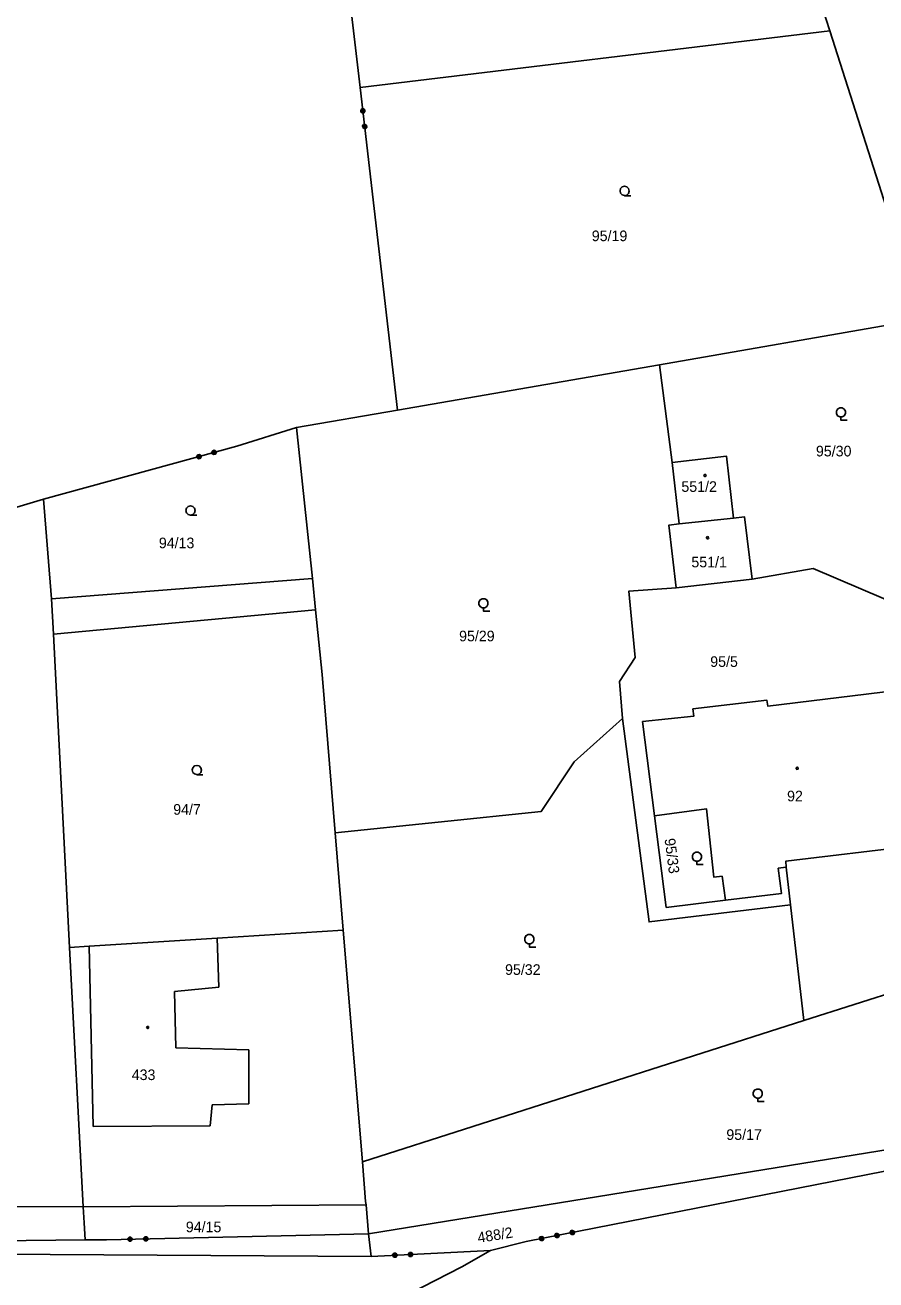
# Model space of a CAD drawing. Extents: x -757994 to -755874, y -1047691 to -1046119.
# Drawn here: x -757159.2 to -757091.1, y -1047392.5 to -1047292 of the extents above; entities that cross this region are included whole.
import ezdxf

# ---------------------------------------------------------------- set-up
doc = ezdxf.new("R2010")
doc.units = 0
doc.layers.add('katastrální mapa', color=7, linetype='Continuous')

msp = doc.modelspace()

# ---------------------------------------------------------------- linework, layer by layer
at = {"layer": 'katastrální mapa'}
for p, q in [((-757133.98, -1047283.45), (-757132.41, -1047297.02)), ((-757094.83, -1047292.5), (-757096.23, -1047288.12)), ((-757094.83, -1047292.5), (-757132.41, -1047297.02)), ((-757087.45, -1047315.58), (-757094.83, -1047292.5)), ((-757132.41, -1047297.02), (-757129.42, -1047322.85)), ((-757087.45, -1047315.58), (-757108.45, -1047319.22)), ((-757108.45, -1047319.22), (-757129.42, -1047322.85)), ((-757108.45, -1047319.22), (-757107.43, -1047327.04)), ((-757129.42, -1047322.85), (-757137.5, -1047324.25)), ((-757137.5, -1047324.25), (-757142.27, -1047325.75)), ((-757137.5, -1047324.25), (-757136.22, -1047336.33)), ((-757142.27, -1047325.75), (-757157.75, -1047329.98)), ((-757106.87, -1047331.97), (-757107.43, -1047327.04)), ((-757157.75, -1047329.98), (-757166.62, -1047332.62)), ((-757157.75, -1047329.98), (-757157.11, -1047337.95)), ((-757106.87, -1047331.97), (-757102.52, -1047331.51)), ((-757157.11, -1047337.95), (-757136.22, -1047336.33)), ((-757136.22, -1047336.33), (-757135.97, -1047338.84)), ((-757101.04, -1047336.38), (-757107.11, -1047337.08)), ((-757157.11, -1047337.95), (-757156.96, -1047340.78)), ((-757156.96, -1047340.78), (-757135.97, -1047338.84)), ((-757135.97, -1047338.84), (-757135.45, -1047344.01)), ((-757155.66, -1047365.86), (-757156.96, -1047340.78)), ((-757135.45, -1047344.01), (-757134.4, -1047356.7)), ((-757108.85, -1047355.32), (-757109.81, -1047347.77)), ((-757134.4, -1047356.7), (-757133.76, -1047364.47)), ((-757098.31, -1047359.44), (-757098.96, -1047359.53)), ((-757098.31, -1047359.44), (-757097.97, -1047362.46)), ((-757103.43, -1047360.15), (-757103.16, -1047362.08)), ((-757097.97, -1047362.46), (-757096.89, -1047371.72)), ((-757143.84, -1047365.11), (-757133.76, -1047364.47)), ((-757133.76, -1047364.47), (-757132.23, -1047383.02)), ((-757154.11, -1047365.76), (-757143.84, -1047365.11)), ((-757143.84, -1047365.11), (-757143.72, -1047369.05)), ((-757155.66, -1047365.86), (-757154.11, -1047365.76)), ((-757155.66, -1047365.86), (-757154.58, -1047386.63)), ((-757153.79, -1047380.19), (-757154.11, -1047365.76)), ((-757080.55, -1047366.5), (-757096.89, -1047371.72)), ((-757143.72, -1047369.05), (-757147.27, -1047369.39)), ((-757147.27, -1047369.39), (-757147.16, -1047373.89)), ((-757096.89, -1047371.72), (-757132.23, -1047383.02)), ((-757147.16, -1047373.89), (-757141.32, -1047374.07)), ((-757141.32, -1047374.07), (-757141.31, -1047378.37)), ((-757144.24, -1047378.47), (-757144.4, -1047380.15)), ((-757141.31, -1047378.37), (-757144.24, -1047378.47)), ((-757144.4, -1047380.15), (-757153.79, -1047380.19)), ((-757131.75, -1047388.8), (-757088.32, -1047381.73)), ((-757132.23, -1047383.02), (-757131.97, -1047386.19)), ((-757119.12, -1047389.4), (-757089.06, -1047383.51)), ((-757154.58, -1047386.63), (-757176.95, -1047386.56)), ((-757154.58, -1047386.63), (-757131.94, -1047386.46)), ((-757131.97, -1047386.19), (-757131.94, -1047386.46)), ((-757131.94, -1047386.46), (-757131.75, -1047388.8)), ((-757154.58, -1047386.63), (-757154.49, -1047387.91)), ((-757154.43, -1047389.27), (-757154.49, -1047387.91)), ((-757176.93, -1047389.56), (-757154.43, -1047389.27)), ((-757154.43, -1047389.27), (-757152.72, -1047389.26)), ((-757152.72, -1047389.26), (-757131.75, -1047388.8)), ((-757131.75, -1047388.8), (-757131.52, -1047390.59)), ((-757121.98, -1047390.12), (-757119.12, -1047389.4)), ((-757131.52, -1047390.59), (-757181.2, -1047390.32)), ((-757131.52, -1047390.59), (-757121.98, -1047390.12)), ((-757124.28, -1047391.44), (-757121.98, -1047390.12)), ((-757128.48, -1047393.6), (-757124.28, -1047391.44))]:
    msp.add_line(p, q, dxfattribs=at)
for points in [[(-757132.03, -1047298.95), (-757132.11, -1047299.06), (-757132.24, -1047299.07), (-757132.35, -1047298.99), (-757132.36, -1047298.86), (-757132.28, -1047298.75), (-757132.15, -1047298.74), (-757132.04, -1047298.82), (-757132.03, -1047298.95), (-757132.05, -1047298.95), (-757132.06, -1047298.83), (-757132.1, -1047298.8), (-757132.08, -1047299), (-757132.12, -1047299.04), (-757132.15, -1047298.76), (-757132.19, -1047298.77), (-757132.16, -1047299.04), (-757132.2, -1047299.05), (-757132.23, -1047298.77), (-757132.27, -1047298.78), (-757132.24, -1047299.05), (-757132.28, -1047299.02), (-757132.3, -1047298.82), (-757132.34, -1047298.86), (-757132.32, -1047298.98)], [(-757131.88, -1047300.2), (-757131.96, -1047300.3), (-757132.1, -1047300.32), (-757132.2, -1047300.23), (-757132.22, -1047300.1), (-757132.14, -1047299.99), (-757132, -1047299.98), (-757131.9, -1047300.06), (-757131.88, -1047300.2), (-757131.9, -1047300.18), (-757131.92, -1047300.06), (-757131.96, -1047300.03), (-757131.94, -1047300.23), (-757131.97, -1047300.27), (-757132.01, -1047299.99), (-757132.04, -1047300), (-757132.01, -1047300.28), (-757132.05, -1047300.28), (-757132.08, -1047300), (-757132.12, -1047300.01), (-757132.09, -1047300.29), (-757132.14, -1047300.25), (-757132.16, -1047300.05), (-757132.19, -1047300.1), (-757132.18, -1047300.21)], [(-757111.24, -1047305.68), (-757111.43, -1047305.63), (-757111.57, -1047305.5), (-757111.61, -1047305.31), (-757111.57, -1047305.12), (-757111.43, -1047304.99), (-757111.24, -1047304.94), (-757111.06, -1047304.99), (-757110.93, -1047305.12), (-757110.88, -1047305.32), (-757110.93, -1047305.51), (-757111.06, -1047305.64), (-757111.25, -1047305.69), (-757110.75, -1047305.69)], [(-757093.93, -1047323.4), (-757094.03, -1047323.4), (-757094.2, -1047323.3), (-757094.29, -1047323.13), (-757094.29, -1047322.94), (-757094.2, -1047322.77), (-757094.03, -1047322.67), (-757093.83, -1047322.67), (-757093.66, -1047322.77), (-757093.57, -1047322.94), (-757093.57, -1047323.13), (-757093.66, -1047323.3), (-757093.83, -1047323.4), (-757093.93, -1047323.4), (-757093.93, -1047323.66), (-757093.43, -1047323.66)], [(-757144.12, -1047326.42), (-757144.24, -1047326.36), (-757144.28, -1047326.23), (-757144.21, -1047326.11), (-757144.08, -1047326.07), (-757143.96, -1047326.14), (-757143.93, -1047326.27), (-757143.99, -1047326.39), (-757144.12, -1047326.42), (-757144.12, -1047326.4), (-757144.01, -1047326.37), (-757143.98, -1047326.32), (-757144.17, -1047326.37), (-757144.22, -1047326.35), (-757143.95, -1047326.27), (-757143.96, -1047326.23), (-757144.23, -1047326.31), (-757144.24, -1047326.27), (-757143.97, -1047326.19), (-757143.98, -1047326.16), (-757144.25, -1047326.23), (-757144.23, -1047326.18), (-757144.03, -1047326.13), (-757144.08, -1047326.1), (-757144.2, -1047326.13)], [(-757145.33, -1047326.75), (-757145.45, -1047326.68), (-757145.48, -1047326.55), (-757145.41, -1047326.44), (-757145.28, -1047326.4), (-757145.17, -1047326.47), (-757145.13, -1047326.6), (-757145.2, -1047326.72), (-757145.33, -1047326.75), (-757145.32, -1047326.73), (-757145.2, -1047326.7), (-757145.18, -1047326.65), (-757145.37, -1047326.7), (-757145.42, -1047326.67), (-757145.15, -1047326.6), (-757145.16, -1047326.56), (-757145.43, -1047326.63), (-757145.44, -1047326.6), (-757145.17, -1047326.52), (-757145.18, -1047326.48), (-757145.45, -1047326.56), (-757145.42, -1047326.51), (-757145.23, -1047326.45), (-757145.28, -1047326.43), (-757145.39, -1047326.46)], [(-757107.43, -1047327.04), (-757103.1, -1047326.54), (-757102.52, -1047331.51)], [(-757145.98, -1047331.25), (-757146.17, -1047331.2), (-757146.3, -1047331.07), (-757146.35, -1047330.88), (-757146.3, -1047330.7), (-757146.17, -1047330.56), (-757145.98, -1047330.51), (-757145.8, -1047330.56), (-757145.67, -1047330.7), (-757145.61, -1047330.89), (-757145.67, -1047331.08), (-757145.8, -1047331.21), (-757145.99, -1047331.26), (-757145.49, -1047331.26)], [(-757107.11, -1047337.08), (-757107.71, -1047332.07), (-757106.87, -1047331.97)], [(-757102.52, -1047331.51), (-757101.65, -1047331.39), (-757101.04, -1047336.38)], [(-757101.04, -1047336.38), (-757096.14, -1047335.54), (-757082.9, -1047341.2)], [(-757111.4, -1047347.55), (-757111.66, -1047344.59), (-757110.39, -1047342.66), (-757110.9, -1047337.34), (-757107.11, -1047337.08)], [(-757122.54, -1047338.67), (-757122.64, -1047338.67), (-757122.81, -1047338.58), (-757122.9, -1047338.41), (-757122.9, -1047338.22), (-757122.81, -1047338.04), (-757122.64, -1047337.95), (-757122.44, -1047337.95), (-757122.27, -1047338.04), (-757122.18, -1047338.22), (-757122.18, -1047338.41), (-757122.27, -1047338.58), (-757122.44, -1047338.67), (-757122.54, -1047338.67), (-757122.54, -1047338.94), (-757122.04, -1047338.94)], [(-757109.81, -1047347.77), (-757105.7, -1047347.34), (-757105.77, -1047346.77), (-757099.87, -1047346.07), (-757099.78, -1047346.54), (-757089.52, -1047345.31), (-757089.13, -1047349.43), (-757087.19, -1047349.2), (-757086.17, -1047349.84)], [(-757134.4, -1047356.7), (-757117.92, -1047354.98), (-757115.27, -1047351), (-757111.4, -1047347.55)], [(-757111.4, -1047347.55), (-757109.28, -1047363.82), (-757097.97, -1047362.46)], [(-757086.17, -1047349.84), (-757085.87, -1047352.5), (-757086.64, -1047353.43), (-757088.55, -1047353.69), (-757088.06, -1047357.72), (-757098.35, -1047358.96), (-757098.31, -1047359.44)], [(-757145.48, -1047352.03), (-757145.67, -1047351.98), (-757145.8, -1047351.85), (-757145.85, -1047351.66), (-757145.8, -1047351.48), (-757145.67, -1047351.34), (-757145.48, -1047351.29), (-757145.3, -1047351.34), (-757145.17, -1047351.48), (-757145.11, -1047351.67), (-757145.17, -1047351.86), (-757145.3, -1047351.99), (-757145.49, -1047352.04), (-757144.99, -1047352.04)], [(-757103.43, -1047360.15), (-757104.09, -1047360.24), (-757104.69, -1047354.76), (-757108.85, -1047355.32)], [(-757108.85, -1047355.32), (-757107.91, -1047362.66), (-757103.16, -1047362.08)], [(-757105.46, -1047358.97), (-757105.55, -1047358.97), (-757105.73, -1047358.87), (-757105.82, -1047358.7), (-757105.82, -1047358.51), (-757105.73, -1047358.34), (-757105.55, -1047358.24), (-757105.36, -1047358.24), (-757105.19, -1047358.34), (-757105.1, -1047358.51), (-757105.1, -1047358.7), (-757105.19, -1047358.87), (-757105.36, -1047358.97), (-757105.46, -1047358.97), (-757105.46, -1047359.23), (-757104.96, -1047359.23)], [(-757103.16, -1047362.08), (-757098.68, -1047361.54), (-757098.96, -1047359.53)], [(-757118.87, -1047365.57), (-757118.97, -1047365.57), (-757119.14, -1047365.47), (-757119.23, -1047365.3), (-757119.23, -1047365.11), (-757119.14, -1047364.93), (-757118.97, -1047364.84), (-757118.77, -1047364.84), (-757118.6, -1047364.93), (-757118.51, -1047365.11), (-757118.51, -1047365.3), (-757118.6, -1047365.47), (-757118.77, -1047365.57), (-757118.86, -1047365.57), (-757118.86, -1047365.83), (-757118.36, -1047365.83)], [(-757100.58, -1047377.92), (-757100.67, -1047377.92), (-757100.85, -1047377.83), (-757100.94, -1047377.66), (-757100.94, -1047377.47), (-757100.85, -1047377.29), (-757100.67, -1047377.2), (-757100.48, -1047377.2), (-757100.31, -1047377.29), (-757100.22, -1047377.47), (-757100.22, -1047377.66), (-757100.31, -1047377.83), (-757100.48, -1047377.92), (-757100.58, -1047377.92), (-757100.58, -1047378.19), (-757100.08, -1047378.19)], [(-757115.4, -1047388.51), (-757115.29, -1047388.58), (-757115.26, -1047388.72), (-757115.33, -1047388.83), (-757115.47, -1047388.85), (-757115.58, -1047388.78), (-757115.6, -1047388.65), (-757115.53, -1047388.53), (-757115.4, -1047388.51), (-757115.41, -1047388.53), (-757115.53, -1047388.55), (-757115.55, -1047388.6), (-757115.37, -1047388.56), (-757115.32, -1047388.59), (-757115.57, -1047388.64), (-757115.57, -1047388.68), (-757115.31, -1047388.63), (-757115.3, -1047388.67), (-757115.56, -1047388.72), (-757115.56, -1047388.76), (-757115.3, -1047388.71), (-757115.31, -1047388.76), (-757115.51, -1047388.8), (-757115.48, -1047388.83), (-757115.36, -1047388.81)], [(-757150.76, -1047389.06), (-757150.66, -1047389.15), (-757150.66, -1047389.28), (-757150.75, -1047389.38), (-757150.89, -1047389.38), (-757150.98, -1047389.29), (-757150.99, -1047389.16), (-757150.89, -1047389.06), (-757150.76, -1047389.06), (-757150.76, -1047389.08), (-757150.88, -1047389.08), (-757150.92, -1047389.12), (-757150.72, -1047389.12), (-757150.68, -1047389.16), (-757150.96, -1047389.16), (-757150.96, -1047389.2), (-757150.68, -1047389.2), (-757150.68, -1047389.24), (-757150.96, -1047389.24), (-757150.96, -1047389.28), (-757150.68, -1047389.28), (-757150.72, -1047389.32), (-757150.92, -1047389.32), (-757150.88, -1047389.36), (-757150.76, -1047389.36)], [(-757149.51, -1047389.03), (-757149.41, -1047389.12), (-757149.41, -1047389.26), (-757149.5, -1047389.35), (-757149.64, -1047389.36), (-757149.73, -1047389.26), (-757149.74, -1047389.13), (-757149.64, -1047389.03), (-757149.51, -1047389.03), (-757149.52, -1047389.05), (-757149.64, -1047389.05), (-757149.68, -1047389.09), (-757149.48, -1047389.09), (-757149.44, -1047389.13), (-757149.72, -1047389.13), (-757149.72, -1047389.17), (-757149.44, -1047389.17), (-757149.44, -1047389.21), (-757149.72, -1047389.21), (-757149.72, -1047389.25), (-757149.44, -1047389.25), (-757149.48, -1047389.29), (-757149.68, -1047389.29), (-757149.64, -1047389.33), (-757149.52, -1047389.33)], [(-757117.86, -1047388.99), (-757117.75, -1047389.06), (-757117.72, -1047389.2), (-757117.8, -1047389.31), (-757117.93, -1047389.33), (-757118.04, -1047389.26), (-757118.07, -1047389.13), (-757117.99, -1047389.02), (-757117.86, -1047388.99), (-757117.85, -1047389.01), (-757117.97, -1047389.03), (-757118, -1047389.08), (-757117.8, -1047389.04), (-757117.77, -1047389.07), (-757118.03, -1047389.13), (-757118.02, -1047389.16), (-757117.76, -1047389.11), (-757117.75, -1047389.15), (-757118.01, -1047389.2), (-757118, -1047389.24), (-757117.74, -1047389.19), (-757117.76, -1047389.24), (-757117.97, -1047389.28), (-757117.93, -1047389.31), (-757117.79, -1047389.28)], [(-757116.63, -1047388.75), (-757116.52, -1047388.82), (-757116.49, -1047388.96), (-757116.57, -1047389.07), (-757116.7, -1047389.09), (-757116.81, -1047389.02), (-757116.84, -1047388.89), (-757116.76, -1047388.77), (-757116.63, -1047388.75), (-757116.63, -1047388.77), (-757116.75, -1047388.79), (-757116.78, -1047388.84), (-757116.58, -1047388.8), (-757116.54, -1047388.83), (-757116.81, -1047388.89), (-757116.8, -1047388.93), (-757116.53, -1047388.87), (-757116.52, -1047388.91), (-757116.8, -1047388.96), (-757116.79, -1047389), (-757116.51, -1047388.95), (-757116.54, -1047389), (-757116.74, -1047389.04), (-757116.69, -1047389.07), (-757116.58, -1047389.04)], [(-757129.57, -1047390.33), (-757129.47, -1047390.42), (-757129.46, -1047390.56), (-757129.55, -1047390.66), (-757129.68, -1047390.66), (-757129.78, -1047390.57), (-757129.79, -1047390.44), (-757129.7, -1047390.34), (-757129.57, -1047390.33), (-757129.57, -1047390.35), (-757129.69, -1047390.36), (-757129.73, -1047390.4), (-757129.53, -1047390.39), (-757129.49, -1047390.43), (-757129.77, -1047390.44), (-757129.76, -1047390.48), (-757129.48, -1047390.47), (-757129.48, -1047390.51), (-757129.76, -1047390.52), (-757129.76, -1047390.56), (-757129.48, -1047390.55), (-757129.52, -1047390.59), (-757129.72, -1047390.6), (-757129.68, -1047390.64), (-757129.56, -1047390.63)], [(-757128.32, -1047390.27), (-757128.22, -1047390.36), (-757128.21, -1047390.5), (-757128.3, -1047390.6), (-757128.44, -1047390.6), (-757128.54, -1047390.51), (-757128.54, -1047390.38), (-757128.45, -1047390.28), (-757128.32, -1047390.27), (-757128.33, -1047390.29), (-757128.45, -1047390.3), (-757128.49, -1047390.34), (-757128.29, -1047390.33), (-757128.25, -1047390.37), (-757128.53, -1047390.38), (-757128.52, -1047390.42), (-757128.24, -1047390.41), (-757128.24, -1047390.45), (-757128.52, -1047390.46), (-757128.52, -1047390.5), (-757128.24, -1047390.49), (-757128.28, -1047390.53), (-757128.48, -1047390.54), (-757128.44, -1047390.58), (-757128.32, -1047390.57)]]:
    msp.add_lwpolyline(points, dxfattribs=at)
for points in [[(-757104.8, -1047328), (-757104.75, -1047328.01), (-757104.73, -1047328.06), (-757104.72, -1047328.09), (-757104.73, -1047328.14), (-757104.77, -1047328.17), (-757104.8, -1047328.18), (-757104.85, -1047328.16), (-757104.88, -1047328.13), (-757104.89, -1047328.09), (-757104.88, -1047328.04), (-757104.84, -1047328.01)], [(-757104.6, -1047332.98), (-757104.55, -1047332.99), (-757104.52, -1047333.04), (-757104.51, -1047333.07), (-757104.52, -1047333.12), (-757104.57, -1047333.15), (-757104.6, -1047333.16), (-757104.65, -1047333.14), (-757104.68, -1047333.11), (-757104.69, -1047333.07), (-757104.68, -1047333.02), (-757104.64, -1047332.99)], [(-757097.43, -1047351.44), (-757097.38, -1047351.45), (-757097.35, -1047351.49), (-757097.35, -1047351.52), (-757097.35, -1047351.57), (-757097.4, -1047351.6), (-757097.43, -1047351.61), (-757097.48, -1047351.59), (-757097.51, -1047351.56), (-757097.52, -1047351.52), (-757097.51, -1047351.48), (-757097.47, -1047351.44)], [(-757149.41, -1047372.18), (-757149.36, -1047372.19), (-757149.34, -1047372.23), (-757149.33, -1047372.26), (-757149.34, -1047372.3), (-757149.38, -1047372.34), (-757149.41, -1047372.35), (-757149.46, -1047372.33), (-757149.49, -1047372.3), (-757149.5, -1047372.26), (-757149.49, -1047372.22), (-757149.45, -1047372.18)]]:
    msp.add_lwpolyline(points, close=True, dxfattribs=at)

# ---------------------------------------------------------------- texts
for s, p in [('95/19', (-757113.87, -1047309.33)), ('95/30', (-757095.93, -1047326.56)), ('551/2', (-757106.7, -1047329.4)), ('94/13', (-757148.52, -1047333.91)), ('551/1', (-757105.9, -1047335.44)), ('95/29', (-757124.49, -1047341.36)), ('95/5', (-757104.39, -1047343.41)), ('92', (-757098.24, -1047354.17)), ('94/7', (-757147.37, -1047355.24)), ('95/32', (-757120.81, -1047368.06)), ('433', (-757150.69, -1047376.48)), ('95/17', (-757103.1, -1047381.27)), ('94/15', (-757146.36, -1047388.66))]:
    msp.add_text(s, height=0.85, dxfattribs=at).set_placement(p)
for s, rotation, p in [('95/33', 277.4262, (-757108.05, -1047357.18)), ('488/2', 8.9954, (-757122.95, -1047389.52))]:
    msp.add_text(s, height=0.85, rotation=rotation, dxfattribs=at).set_placement(p)

doc.saveas('drawing.dxf')
